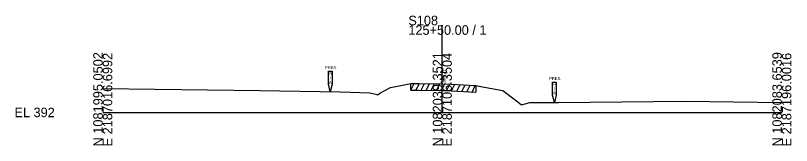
# Model space of a CAD drawing. Extents: x -26 to 2203, y 490 to 19581.
# Drawn here: x 1974.3 to 2202.8, y 4490.3 to 4528.4 of the extents above; entities that cross this region are included whole.
import ezdxf

# ---------------------------------------------------------------- set-up
doc = ezdxf.new("R2010")
doc.units = 0
for name, color, linetype in [('RD_GPK_XS_Cell', 7, 'Continuous'), ('RD_XS_ExGround', 7, 'Continuous'), ('RD_XS_ExPaveRet', 7, 'Continuous'), ('RD_XS_ExRW', 7, 'Continuous'), ('RD_XS_TX_Elev_EX', 7, 'Continuous')]:
    doc.layers.add(name, color=color, linetype=linetype)

msp = doc.modelspace()

# ---------------------------------------------------------------- linework, layer by layer
at = {"layer": 'RD_GPK_XS_Cell'}
for p, q in [((2100, 4500), (2100, 4525.58)), ((2000, 4500), (2100, 4500)), ((2100, 4500), (2200, 4500))]:
    msp.add_line(p, q, dxfattribs=at)
at = {"layer": 'RD_XS_ExGround'}
msp.add_lwpolyline([(2000, 4506.97), (2046.31, 4506.4), (2069.9, 4506.01), (2078.68, 4505.79), (2080.4, 4505.4), (2080.93, 4505.16), (2081.79, 4505.7), (2084.77, 4507.3), (2086.31, 4507.62), (2090.75, 4508.53), (2093.07, 4508.49), (2100.2, 4508.42), (2102.59, 4508.3), (2109.89, 4507.91), (2111.87, 4507.51), (2117.8, 4506.43), (2121.83, 4503.43), (2123.34, 4502.23), (2124, 4502.41), (2125.78, 4502.93), (2134.21, 4502.89), (2171.52, 4503.31), (2200, 4502.92)], dxfattribs=at)
at = {"layer": 'RD_XS_ExPaveRet'}
for p, q in [((2090.75, 4506.53), (2090.75, 4508.53)), ((2090.75, 4506.53), (2091.74, 4508.51)), ((2092.25, 4506.5), (2093.24, 4508.49)), ((2093.75, 4506.48), (2094.74, 4508.47)), ((2095.25, 4506.47), (2096.24, 4508.46)), ((2096.75, 4506.45), (2097.74, 4508.44)), ((2098.25, 4506.44), (2099.24, 4508.43)), ((2099.75, 4506.42), (2100.73, 4508.39)), ((2101.25, 4506.36), (2102.23, 4508.32)), ((2102.75, 4506.29), (2103.72, 4508.24)), ((2104.25, 4506.21), (2105.22, 4508.16)), ((2105.75, 4506.13), (2106.72, 4508.08)), ((2107.25, 4506.05), (2108.22, 4508)), ((2108.75, 4505.97), (2109.72, 4507.92)), ((2109.89, 4507.91), (2109.89, 4505.91)), ((2090.75, 4506.53), (2093.07, 4506.49)), ((2093.07, 4506.49), (2100.2, 4506.42)), ((2100.2, 4506.42), (2102.59, 4506.3)), ((2102.59, 4506.3), (2109.89, 4505.91))]:
    msp.add_line(p, q, dxfattribs=at)
at = {"layer": 'RD_XS_ExRW'}
for points in [[(2066.45, 4512.08), (2067.55, 4512.08), (2067.55, 4508.25), (2067, 4506.06), (2066.45, 4508.25)], [(2132.45, 4508.91), (2133.55, 4508.91), (2133.55, 4505.08), (2133, 4502.9), (2132.45, 4505.08)]]:
    msp.add_lwpolyline(points, close=True, dxfattribs=at)

# ---------------------------------------------------------------- texts
at = {"layer": 'RD_GPK_XS_Cell'}
for s, p in [('S108', (2090, 4525.58)), ('125+50.00 / 1', (2090, 4522.78)), ('EL 392', (1974, 4498.6))]:
    msp.add_text(s, height=2.8, dxfattribs=at).set_placement(p)
for s, p in [('N 1081995.0502', (2000, 4490)), ('E 2187016.6992', (2002.8, 4490)), ('N 1082039.3521', (2100, 4490)), ('E 2187106.3504', (2102.8, 4490)), ('N 1082083.6539', (2200, 4490)), ('E 2187196.0016', (2202.8, 4490))]:
    msp.add_text(s, height=2.8, rotation=90, dxfattribs=at).set_placement(p)
at = {"layer": 'RD_XS_ExRW'}
for s, p in [('PRES.', (2065.45, 4512.7)), ('R', (2066.71, 4510.98)), ('W', (2066.53, 4508.36)), ('/', (2066.83, 4509.67)), ('PRES.', (2131.45, 4509.54)), ('R', (2132.71, 4507.82)), ('/', (2132.83, 4506.51)), ('W', (2132.53, 4505.2))]:
    msp.add_text(s, height=0.875, dxfattribs=at).set_placement(p)
at = {"layer": 'RD_XS_TX_Elev_EX'}
msp.add_text('396.21', height=1, rotation=90, dxfattribs=at).set_placement((2101, 4508.42))

doc.saveas('drawing.dxf')
